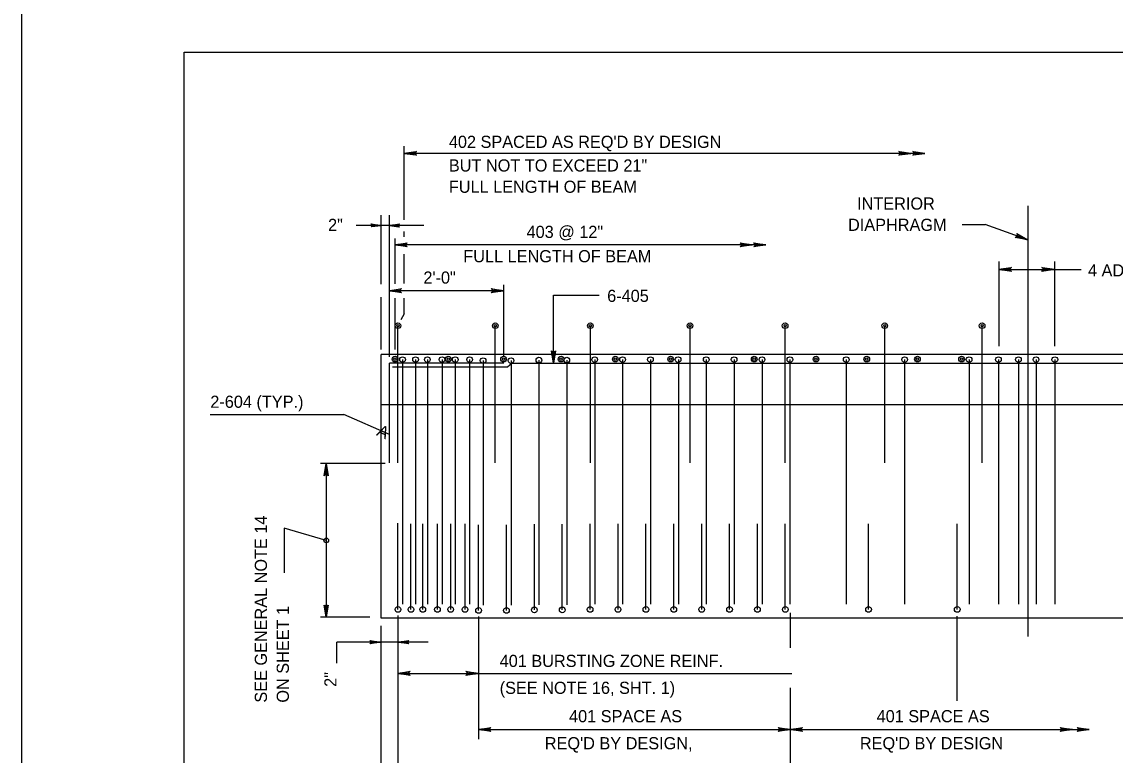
# Model space of a CAD drawing. Extents: x 637933 to 640019, y 298854 to 300042.
# Drawn here: x 637983.9 to 638253.5, y 299259.7 to 299440.6 of the extents above; entities that cross this region are included whole.
import ezdxf

# ---------------------------------------------------------------- set-up
doc = ezdxf.new("R2010")
doc.units = 0
doc.layers.add('1', color=7, linetype='Continuous')
doc.layers.add('PLT-BNDY', color=7, linetype='Continuous')

msp = doc.modelspace()

# ---------------------------------------------------------------- linework, layer by layer
at = {"layer": '1'}
for p, q in [((638023.93, 298869.12), (638023.93, 299433.12)), ((638023.93, 299433.12), (638809.94, 299433.12)), ((638078.22, 299391.78), (638078.22, 299409.92)), ((638206.58, 299408.17), (638078.22, 299408.17)), ((638231.96, 299395.21), (638231.96, 299288.98)), ((638072.53, 299375.88), (638072.53, 299392.9)), ((638074.53, 299359.78), (638074.53, 299392.9)), ((638083.04, 299390.4), (638066.36, 299390.4)), ((638078.22, 299387.54), (638078.22, 299388.89)), ((638215.72, 299390.58), (638221.43, 299390.58)), ((638231.96, 299386.81), (638221.43, 299390.58)), ((638075.94, 299375.99), (638075.94, 299387.15)), ((638167.35, 299385.6), (638075.94, 299385.6)), ((638078.22, 299376.1), (638078.22, 299383.29)), ((638224.76, 299381.47), (638224.76, 299360.57)), ((638238.51, 299381.47), (638238.51, 299360.57)), ((638224.76, 299379.54), (638245.11, 299379.54)), ((638074.53, 299357.93), (638074.53, 299375.73)), ((638102.78, 299357.93), (638102.78, 299375.73)), ((638072.53, 299359.78), (638072.53, 299372.68)), ((638102.78, 299374.23), (638074.53, 299374.23)), ((638075.94, 299359.76), (638075.94, 299372.46)), ((638078.22, 299368.6), (638078.22, 299372.46)), ((638115.02, 299357.01), (638115.02, 299373.17)), ((638115.02, 299373.17), (638126.28, 299373.17)), ((638078.22, 299368.6), (638077.4, 299367.09)), ((638076.65, 299331.81), (638076.65, 299365.65)), ((638076.65, 299365.65), (638076.65, 299365.65)), ((638076.65, 299365.65), (638076.65, 299365.65)), ((638076.65, 299365.65), (638076.65, 299365.65)), ((638076.65, 299365.65), (638076.65, 299365.65)), ((638100.65, 299331.81), (638100.65, 299365.65)), ((638100.65, 299365.65), (638100.65, 299365.65)), ((638100.65, 299365.65), (638100.65, 299365.65)), ((638100.65, 299365.65), (638100.65, 299365.65)), ((638100.65, 299365.65), (638100.65, 299365.65)), ((638124.09, 299331.81), (638124.09, 299365.65)), ((638124.65, 299365.65), (638124.65, 299365.65)), ((638124.65, 299365.65), (638124.65, 299365.65)), ((638124.65, 299365.65), (638124.65, 299365.65)), ((638124.65, 299365.65), (638124.65, 299365.65)), ((638148.65, 299331.81), (638148.65, 299365.65)), ((638148.65, 299365.65), (638148.65, 299365.65)), ((638148.65, 299365.65), (638148.65, 299365.65)), ((638148.65, 299365.65), (638148.65, 299365.65)), ((638148.65, 299365.65), (638148.65, 299365.65)), ((638172.09, 299331.81), (638172.09, 299365.65)), ((638172.65, 299365.65), (638172.65, 299365.65)), ((638172.65, 299365.65), (638172.65, 299365.65)), ((638172.65, 299365.65), (638172.65, 299365.65)), ((638172.65, 299365.65), (638172.65, 299365.65)), ((638196.65, 299331.81), (638196.65, 299365.65)), ((638196.65, 299365.65), (638196.65, 299365.65)), ((638196.65, 299365.65), (638196.65, 299365.65)), ((638196.65, 299365.65), (638196.65, 299365.65)), ((638196.65, 299365.65), (638196.65, 299365.65)), ((638220.65, 299331.81), (638220.65, 299365.65)), ((638220.65, 299365.65), (638220.65, 299365.65)), ((638220.65, 299365.65), (638220.65, 299365.65)), ((638220.65, 299365.65), (638220.65, 299365.65)), ((638220.65, 299365.65), (638220.65, 299365.65)), ((638072.53, 299293.53), (638072.53, 299358.53)), ((638298.76, 299358.53), (638072.53, 299358.53)), ((638074.53, 299331.81), (638074.53, 299356.43)), ((638102.78, 299356.43), (638074.53, 299356.43)), ((638075.94, 299357.4), (638075.94, 299357.4)), ((638075.94, 299357.4), (638075.94, 299357.4)), ((638075.94, 299357.4), (638075.94, 299357.4)), ((638075.94, 299357.4), (638075.94, 299357.4)), ((638077.78, 299357.28), (638077.78, 299357.28)), ((638077.78, 299357.28), (638077.78, 299357.28)), ((638077.78, 299357.28), (638077.78, 299357.28)), ((638077.78, 299357.28), (638077.78, 299357.28)), ((638077.78, 299357.28), (638077.78, 299296.94)), ((638080.98, 299357.28), (638080.98, 299357.28)), ((638080.98, 299357.28), (638080.98, 299357.28)), ((638080.98, 299357.28), (638080.98, 299357.28)), ((638080.98, 299357.28), (638080.98, 299357.28)), ((638080.98, 299357.28), (638080.98, 299296.94)), ((638083.9, 299357.28), (638083.9, 299357.28)), ((638083.9, 299357.28), (638083.9, 299357.28)), ((638083.9, 299357.28), (638083.9, 299357.28)), ((638083.9, 299357.28), (638083.9, 299357.28)), ((638083.9, 299357.28), (638083.9, 299296.94)), ((638087.51, 299357.28), (638087.51, 299357.28)), ((638087.51, 299357.28), (638087.51, 299357.28)), ((638087.51, 299357.28), (638087.51, 299357.28)), ((638087.51, 299357.28), (638087.51, 299357.28)), ((638087.51, 299357.28), (638087.51, 299296.94)), ((638089.05, 299357.4), (638089.05, 299357.4)), ((638089.05, 299357.4), (638089.05, 299357.4)), ((638089.05, 299357.4), (638089.05, 299357.4)), ((638089.05, 299357.4), (638089.05, 299357.4)), ((638090.78, 299357.28), (638090.78, 299357.28)), ((638090.78, 299357.28), (638090.78, 299357.28)), ((638090.78, 299357.28), (638090.78, 299357.28)), ((638090.78, 299357.28), (638090.78, 299357.28)), ((638090.78, 299357.28), (638090.78, 299296.94)), ((638094.32, 299357.28), (638094.32, 299357.28)), ((638094.32, 299357.28), (638094.32, 299357.28)), ((638094.32, 299357.28), (638094.32, 299357.28)), ((638094.32, 299357.28), (638094.32, 299357.28)), ((638094.32, 299357.28), (638094.32, 299296.94)), ((638097.65, 299357.03), (638097.65, 299357.03)), ((638097.65, 299357.03), (638097.65, 299357.03)), ((638097.65, 299357.03), (638097.65, 299357.03)), ((638097.65, 299357.03), (638097.65, 299357.03)), ((638097.65, 299357.03), (638097.65, 299296.69)), ((638102.69, 299357.4), (638102.69, 299357.4)), ((638102.69, 299357.4), (638102.69, 299357.4)), ((638102.69, 299357.4), (638102.69, 299357.4)), ((638102.69, 299357.4), (638102.69, 299357.4)), ((638104.78, 299356.43), (638103.65, 299355.43)), ((638104.53, 299357.03), (638104.53, 299357.03)), ((638104.53, 299357.03), (638104.53, 299357.03)), ((638104.53, 299357.03), (638104.53, 299357.03)), ((638104.53, 299357.03), (638104.53, 299357.03)), ((638104.53, 299357.03), (638104.53, 299296.69)), ((638104.78, 299356.43), (638298.64, 299356.43)), ((638111.4, 299357.15), (638111.4, 299357.15)), ((638111.4, 299357.15), (638111.4, 299357.15)), ((638111.4, 299357.15), (638111.4, 299357.15)), ((638111.4, 299357.15), (638111.4, 299357.15)), ((638111.4, 299357.15), (638111.4, 299296.81)), ((638115.02, 299356.43), (638115.02, 299357.01)), ((638116.87, 299357.4), (638116.87, 299357.4)), ((638116.87, 299357.4), (638116.87, 299357.4)), ((638116.87, 299357.4), (638116.87, 299357.4)), ((638116.87, 299357.4), (638116.87, 299357.4)), ((638118.28, 299357.15), (638118.28, 299357.15)), ((638118.28, 299357.15), (638118.28, 299357.15)), ((638118.28, 299357.15), (638118.28, 299357.15)), ((638118.28, 299357.15), (638118.28, 299357.15)), ((638118.28, 299357.15), (638118.28, 299296.81)), ((638125.15, 299357.28), (638125.15, 299357.28)), ((638125.15, 299357.28), (638125.15, 299357.28)), ((638125.15, 299357.28), (638125.15, 299357.28)), ((638125.15, 299357.28), (638125.15, 299357.28)), ((638125.15, 299357.28), (638125.15, 299296.94)), ((638130.24, 299357.4), (638130.24, 299357.4)), ((638130.24, 299357.4), (638130.24, 299357.4)), ((638130.24, 299357.4), (638130.24, 299357.4)), ((638130.24, 299357.4), (638130.24, 299357.4)), ((638132.03, 299357.28), (638132.03, 299357.28)), ((638132.03, 299357.28), (638132.03, 299357.28)), ((638132.03, 299357.28), (638132.03, 299357.28)), ((638132.03, 299357.28), (638132.03, 299357.28)), ((638132.03, 299357.28), (638132.03, 299296.94)), ((638138.9, 299357.28), (638138.9, 299357.28)), ((638138.9, 299357.28), (638138.9, 299357.28)), ((638138.9, 299357.28), (638138.9, 299357.28)), ((638138.9, 299357.28), (638138.9, 299357.28)), ((638138.9, 299357.28), (638138.9, 299296.94)), ((638143.88, 299357.4), (638143.88, 299357.4)), ((638143.88, 299357.4), (638143.88, 299357.4)), ((638143.88, 299357.4), (638143.88, 299357.4)), ((638143.88, 299357.4), (638143.88, 299357.4)), ((638145.78, 299357.28), (638145.78, 299357.28)), ((638145.78, 299357.28), (638145.78, 299357.28)), ((638145.78, 299357.28), (638145.78, 299357.28)), ((638145.78, 299357.28), (638145.78, 299357.28)), ((638145.78, 299357.28), (638145.78, 299296.94)), ((638151.92, 299357.28), (638151.92, 299357.28)), ((638152.02, 299357.28), (638152.02, 299357.28)), ((638152.21, 299357.28), (638152.21, 299357.28)), ((638152.65, 299357.28), (638152.65, 299357.28)), ((638152.65, 299357.28), (638152.65, 299357.28)), ((638152.65, 299357.28), (638152.65, 299357.28)), ((638152.65, 299357.28), (638152.65, 299357.28)), ((638152.65, 299357.28), (638152.65, 299296.94)), ((638159.53, 299357.28), (638159.53, 299357.28)), ((638159.53, 299357.28), (638159.53, 299357.28)), ((638159.53, 299357.28), (638159.53, 299357.28)), ((638159.53, 299357.28), (638159.53, 299357.28)), ((638159.53, 299357.28), (638159.53, 299296.94)), ((638164.47, 299357.4), (638164.47, 299357.4)), ((638164.47, 299357.4), (638164.47, 299357.4)), ((638164.47, 299357.4), (638164.47, 299357.4)), ((638164.47, 299357.4), (638164.47, 299357.4)), ((638166.4, 299357.28), (638166.4, 299357.28)), ((638166.4, 299357.28), (638166.4, 299357.28)), ((638166.4, 299357.28), (638166.4, 299357.28)), ((638166.4, 299357.28), (638166.4, 299357.28)), ((638166.4, 299357.28), (638166.4, 299296.94)), ((638173.28, 299357.28), (638173.28, 299357.28)), ((638173.28, 299357.28), (638173.28, 299357.28)), ((638173.28, 299357.28), (638173.28, 299357.28)), ((638173.28, 299357.28), (638173.28, 299357.28)), ((638173.28, 299357.28), (638173.28, 299296.94)), ((638179.72, 299357.4), (638179.72, 299357.4)), ((638179.72, 299357.4), (638179.72, 299357.4)), ((638179.72, 299357.4), (638179.72, 299357.4)), ((638179.72, 299357.4), (638179.72, 299357.4)), ((638187.17, 299357.28), (638187.17, 299296.94)), ((638187.17, 299357.28), (638187.17, 299357.28)), ((638187.17, 299357.28), (638187.17, 299357.28)), ((638187.17, 299357.28), (638187.17, 299357.28)), ((638187.17, 299357.28), (638187.17, 299357.28)), ((638192.22, 299357.4), (638192.22, 299357.4)), ((638192.22, 299357.4), (638192.22, 299357.4)), ((638192.22, 299357.4), (638192.22, 299357.4)), ((638192.22, 299357.4), (638192.22, 299357.4)), ((638201.56, 299357.28), (638201.56, 299296.94)), ((638201.56, 299357.28), (638201.56, 299357.28)), ((638201.56, 299357.28), (638201.56, 299357.28)), ((638201.56, 299357.28), (638201.56, 299357.28)), ((638201.56, 299357.28), (638201.56, 299357.28)), ((638204.72, 299357.4), (638204.72, 299357.4)), ((638204.72, 299357.4), (638204.72, 299357.4)), ((638204.72, 299357.4), (638204.72, 299357.4)), ((638204.72, 299357.4), (638204.72, 299357.4)), ((638215.61, 299357.4), (638215.61, 299357.4)), ((638215.61, 299357.4), (638215.61, 299357.4)), ((638215.61, 299357.4), (638215.61, 299357.4)), ((638215.61, 299357.4), (638215.61, 299357.4)), ((638217.22, 299357.4), (638217.22, 299357.4)), ((638217.22, 299357.4), (638217.22, 299357.4)), ((638217.22, 299357.4), (638217.22, 299357.4)), ((638217.47, 299357.28), (638217.47, 299296.94)), ((638217.47, 299357.28), (638217.47, 299357.28)), ((638217.47, 299357.28), (638217.47, 299357.28)), ((638217.47, 299357.28), (638217.47, 299357.28)), ((638217.47, 299357.28), (638217.47, 299357.28)), ((638224.7, 299357.28), (638224.7, 299296.94)), ((638224.7, 299357.28), (638224.7, 299357.28)), ((638224.7, 299357.28), (638224.7, 299357.28)), ((638224.7, 299357.28), (638224.7, 299357.28)), ((638224.7, 299357.28), (638224.7, 299357.28)), ((638229.62, 299357.28), (638229.62, 299296.94)), ((638229.62, 299357.28), (638229.62, 299357.28)), ((638229.62, 299357.28), (638229.62, 299357.28)), ((638229.62, 299357.28), (638229.62, 299357.28)), ((638229.62, 299357.28), (638229.62, 299357.28)), ((638233.96, 299357.28), (638233.96, 299296.94)), ((638233.96, 299357.28), (638233.96, 299357.28)), ((638233.96, 299357.28), (638233.96, 299357.28)), ((638233.96, 299357.28), (638233.96, 299357.28)), ((638233.96, 299357.28), (638233.96, 299357.28)), ((638238.59, 299357.28), (638238.59, 299296.94)), ((638238.59, 299357.28), (638238.59, 299357.28)), ((638238.59, 299357.28), (638238.59, 299357.28)), ((638238.59, 299357.28), (638238.59, 299357.28)), ((638238.59, 299357.28), (638238.59, 299357.28)), ((638103.65, 299355.43), (638075.28, 299355.43)), ((638297.73, 299346.15), (638072.53, 299346.15)), ((638030.36, 299343.75), (638063.31, 299343.75)), ((638074.53, 299338.83), (638063.31, 299343.75)), ((638073.46, 299331.65), (638057.53, 299331.65)), ((638058.98, 299331.65), (638058.98, 299293.73)), ((638076.65, 299295.65), (638076.65, 299316.9)), ((638079.86, 299295.65), (638079.86, 299316.78)), ((638082.78, 299295.65), (638082.78, 299316.78)), ((638086.39, 299295.65), (638086.39, 299316.78)), ((638089.65, 299295.65), (638089.65, 299316.78)), ((638093.19, 299295.65), (638093.19, 299316.78)), ((638096.53, 299295.4), (638096.53, 299316.53)), ((638103.4, 299295.4), (638103.4, 299316.53)), ((638110.28, 299295.53), (638110.28, 299316.65)), ((638117.15, 299295.53), (638117.15, 299316.65)), ((638124.03, 299295.65), (638124.03, 299316.78)), ((638130.9, 299295.65), (638130.9, 299316.78)), ((638137.78, 299295.65), (638137.78, 299316.78)), ((638144.65, 299295.65), (638144.65, 299316.78)), ((638151.53, 299295.65), (638151.53, 299316.78)), ((638158.4, 299295.65), (638158.4, 299316.78)), ((638165.28, 299295.65), (638165.28, 299316.78)), ((638172.15, 299295.65), (638172.15, 299316.78)), ((638192.66, 299295.65), (638192.66, 299316.78)), ((638192.66, 299316.78), (638192.66, 299316.78)), ((638214.53, 299295.65), (638214.53, 299316.78)), ((638058.98, 299312.69), (638048.56, 299315.67)), ((638048.56, 299315.67), (638048.56, 299304.66)), ((638076.65, 299294.15), (638076.65, 299240.18)), ((638173.4, 299286.17), (638173.4, 299294.84)), ((638214.53, 299295.65), (638214.53, 299295.65)), ((638214.53, 299295.65), (638214.53, 299295.65)), ((638214.53, 299295.65), (638214.53, 299295.65)), ((638069.68, 299293.73), (638057.53, 299293.73)), ((638293.89, 299293.53), (638072.53, 299293.53)), ((638072.53, 299227.1), (638072.53, 299291.6)), ((638096.53, 299293.9), (638096.53, 299263.64)), ((638214.53, 299273.1), (638214.53, 299294.01)), ((638072.28, 299287.58), (638061.56, 299287.58)), ((638061.56, 299282.43), (638061.56, 299287.58)), ((638076.65, 299287.58), (638072.28, 299287.58)), ((638084.06, 299287.58), (638076.65, 299287.58)), ((638076.65, 299279.83), (638173.76, 299279.83)), ((638173.4, 299236.01), (638173.4, 299276.34)), ((638096.53, 299266.03), (638173.4, 299266.03)), ((638173.4, 299266.03), (638247.08, 299266.03))]:
    msp.add_line(p, q, dxfattribs=at)
for points in [[(638081.08, 299407.82), (638080.97, 299408.02), (638078.22, 299408.17), (638081.08, 299407.82), (638081.22, 299407.69), (638078.22, 299408.17), (638080.97, 299408.31), (638081.07, 299408.51), (638078.22, 299408.17), (638081.22, 299408.65), (638081.07, 299408.51)], [(638200.26, 299408.53), (638200.36, 299408.33), (638203.11, 299408.17), (638200.26, 299408.53), (638200.11, 299408.66), (638203.11, 299408.17), (638200.37, 299408.04), (638200.27, 299407.83), (638203.11, 299408.17), (638200.11, 299407.7), (638200.27, 299407.83)], [(638203.73, 299408.53), (638203.83, 299408.33), (638206.58, 299408.17), (638203.73, 299408.53), (638203.58, 299408.66), (638206.58, 299408.17), (638203.84, 299408.04), (638203.74, 299407.83), (638206.58, 299408.17), (638203.58, 299407.7), (638203.74, 299407.83)], [(638070.15, 299390.65), (638070.28, 299390.53), (638072.53, 299390.4), (638070.15, 299390.65), (638070.03, 299390.78), (638072.53, 299390.4), (638070.28, 299390.28), (638070.15, 299390.15), (638072.53, 299390.4), (638070.03, 299390.03), (638070.15, 299390.15)], [(638076.9, 299390.03), (638076.78, 299390.28), (638074.53, 299390.4), (638076.9, 299390.03), (638077.03, 299390.03), (638074.53, 299390.4), (638076.78, 299390.53), (638076.9, 299390.65), (638074.53, 299390.4), (638077.03, 299390.78), (638076.9, 299390.65)], [(638078.76, 299385.24), (638078.65, 299385.45), (638075.91, 299385.6), (638078.76, 299385.24), (638078.91, 299385.12), (638075.91, 299385.6), (638078.65, 299385.74), (638078.75, 299385.94), (638075.91, 299385.6), (638078.91, 299386.08), (638078.75, 299385.94)], [(638161.16, 299385.96), (638161.26, 299385.75), (638164.01, 299385.6), (638161.16, 299385.96), (638161.01, 299386.08), (638164.01, 299385.6), (638161.26, 299385.47), (638161.16, 299385.26), (638164.01, 299385.6), (638161.01, 299385.12), (638161.16, 299385.26)], [(638164.5, 299385.96), (638164.61, 299385.75), (638167.35, 299385.6), (638164.5, 299385.96), (638164.35, 299386.08), (638167.35, 299385.6), (638164.61, 299385.47), (638164.51, 299385.26), (638167.35, 299385.6), (638164.35, 299385.12), (638164.51, 299385.26)], [(638229.29, 299388.24), (638229.33, 299387.91), (638231.96, 299386.81), (638229.29, 299388.24), (638229.2, 299388.44), (638231.96, 299386.81), (638229.23, 299387.63), (638229.04, 299387.54), (638231.96, 299386.81), (638228.84, 299387.45), (638229.04, 299387.54)], [(638227.76, 299379.16), (638227.64, 299379.41), (638224.76, 299379.54), (638227.76, 299379.16), (638227.89, 299379.04), (638224.76, 299379.54), (638227.64, 299379.79), (638227.76, 299379.91), (638224.76, 299379.54), (638227.89, 299380.04), (638227.76, 299379.91)], [(638235.51, 299379.91), (638235.63, 299379.79), (638238.51, 299379.54), (638235.51, 299379.91), (638235.38, 299380.04), (638238.51, 299379.54), (638235.63, 299379.41), (638235.51, 299379.29), (638238.51, 299379.54), (638235.38, 299379.04), (638235.51, 299379.29)], [(638077.38, 299373.93), (638077.23, 299374.08), (638074.53, 299374.23), (638077.38, 299373.93), (638077.53, 299373.78), (638074.53, 299374.23), (638077.23, 299374.38), (638077.38, 299374.68), (638074.53, 299374.23), (638077.53, 299374.83), (638077.38, 299374.68)], [(638099.78, 299374.68), (638099.93, 299374.38), (638102.78, 299374.23), (638099.78, 299374.68), (638099.63, 299374.83), (638102.78, 299374.23), (638099.93, 299374.08), (638099.78, 299373.93), (638102.78, 299374.23), (638099.63, 299373.78), (638099.78, 299373.93)], [(638115.37, 299359.28), (638115.17, 299359.18), (638115.02, 299356.43), (638115.37, 299359.28), (638115.5, 299359.43), (638115.02, 299356.43), (638114.88, 299359.17), (638114.68, 299359.27), (638115.02, 299356.43), (638114.54, 299359.43), (638114.68, 299359.27)], [(638058.62, 299328.8), (638058.83, 299328.9), (638058.98, 299331.65), (638058.62, 299328.8), (638058.49, 299328.65), (638058.98, 299331.65), (638059.11, 299328.91), (638059.32, 299328.81), (638058.98, 299331.65), (638059.46, 299328.65), (638059.32, 299328.81)], [(638059.34, 299296.59), (638059.13, 299296.48), (638058.98, 299293.73), (638059.34, 299296.59), (638059.46, 299296.73), (638058.98, 299293.73), (638058.84, 299296.48), (638058.64, 299296.58), (638058.98, 299293.73), (638058.5, 299296.73), (638058.64, 299296.58)], [(638069.9, 299287.83), (638070.03, 299287.7), (638072.28, 299287.58), (638069.9, 299287.83), (638069.78, 299287.95), (638072.28, 299287.58), (638070.03, 299287.45), (638069.9, 299287.33), (638072.28, 299287.58), (638069.78, 299287.2), (638069.9, 299287.33)], [(638079.15, 299287.33), (638079.03, 299287.45), (638076.65, 299287.58), (638079.15, 299287.33), (638079.28, 299287.2), (638076.65, 299287.58), (638079.03, 299287.7), (638079.15, 299287.83), (638076.65, 299287.58), (638079.28, 299287.95), (638079.15, 299287.83)], [(638079.5, 299279.53), (638079.35, 299279.68), (638076.65, 299279.83), (638079.5, 299279.53), (638079.65, 299279.38), (638076.65, 299279.83), (638079.35, 299279.98), (638079.5, 299280.28), (638076.65, 299279.83), (638079.65, 299280.43), (638079.5, 299280.28)], [(638093.53, 299280.28), (638093.68, 299279.98), (638096.53, 299279.83), (638093.53, 299280.28), (638093.38, 299280.43), (638096.53, 299279.83), (638093.68, 299279.68), (638093.53, 299279.53), (638096.53, 299279.83), (638093.38, 299279.38), (638093.53, 299279.53)], [(638099.38, 299265.67), (638099.27, 299265.87), (638096.53, 299266.03), (638099.38, 299265.67), (638099.53, 299265.54), (638096.53, 299266.03), (638099.27, 299266.16), (638099.37, 299266.36), (638096.53, 299266.03), (638099.53, 299266.5), (638099.37, 299266.36)], [(638170.54, 299266.38), (638170.65, 299266.18), (638173.4, 299266.03), (638170.54, 299266.38), (638170.4, 299266.51), (638173.4, 299266.03), (638170.65, 299265.89), (638170.55, 299265.69), (638173.4, 299266.03), (638170.4, 299265.55), (638170.55, 299265.69)], [(638176.25, 299265.67), (638176.15, 299265.87), (638173.4, 299266.03), (638176.25, 299265.67), (638176.4, 299265.54), (638173.4, 299266.03), (638176.14, 299266.16), (638176.24, 299266.36), (638173.4, 299266.03), (638176.4, 299266.5), (638176.24, 299266.36)], [(638240.06, 299266.38), (638240.16, 299266.18), (638242.91, 299266.03), (638240.06, 299266.38), (638239.91, 299266.51), (638242.91, 299266.03), (638240.16, 299265.89), (638240.06, 299265.69), (638242.91, 299266.03), (638239.91, 299265.55), (638240.06, 299265.69)], [(638244.22, 299266.38), (638244.33, 299266.18), (638247.08, 299266.03), (638244.22, 299266.38), (638244.08, 299266.51), (638247.08, 299266.03), (638244.33, 299265.89), (638244.23, 299265.69), (638247.08, 299266.03), (638244.08, 299265.55), (638244.23, 299265.69)]]:
    msp.add_lwpolyline(points, dxfattribs=at)
for centre, radius in [((638076.65, 299365.65), 0.7), ((638076.67, 299365.68), 0.274), ((638100.65, 299365.65), 0.7), ((638100.67, 299365.68), 0.274), ((638124.09, 299365.65), 0.7), ((638124.1, 299365.68), 0.274), ((638148.65, 299365.65), 0.7), ((638148.67, 299365.68), 0.274), ((638172.09, 299365.65), 0.7), ((638172.1, 299365.68), 0.274), ((638196.65, 299365.65), 0.7), ((638196.67, 299365.68), 0.274), ((638220.65, 299365.65), 0.7), ((638220.67, 299365.68), 0.274), ((638075.94, 299357.4), 0.7), ((638075.95, 299357.4), 0.3), ((638077.78, 299357.28), 0.7), ((638080.98, 299357.28), 0.7), ((638083.9, 299357.28), 0.7), ((638087.51, 299357.28), 0.7), ((638089.05, 299357.4), 0.7), ((638089.05, 299357.4), 0.3), ((638090.78, 299357.28), 0.7), ((638094.32, 299357.28), 0.7), ((638097.65, 299357.03), 0.7), ((638102.69, 299357.4), 0.7), ((638102.69, 299357.4), 0.3), ((638104.53, 299357.03), 0.7), ((638111.4, 299357.15), 0.7), ((638116.87, 299357.4), 0.7), ((638116.87, 299357.4), 0.3), ((638118.28, 299357.15), 0.7), ((638125.15, 299357.28), 0.7), ((638130.24, 299357.4), 0.7), ((638130.24, 299357.4), 0.3), ((638132.03, 299357.28), 0.7), ((638138.9, 299357.28), 0.7), ((638143.88, 299357.4), 0.7), ((638143.88, 299357.4), 0.3), ((638145.71, 299357.28), 0.7), ((638152.65, 299357.28), 0.7), ((638159.53, 299357.28), 0.7), ((638164.47, 299357.4), 0.7), ((638164.47, 299357.4), 0.3), ((638166.4, 299357.28), 0.7), ((638173.28, 299357.28), 0.7), ((638179.72, 299357.4), 0.7), ((638179.72, 299357.4), 0.3), ((638187.17, 299357.28), 0.7), ((638192.22, 299357.4), 0.7), ((638192.22, 299357.4), 0.3), ((638201.56, 299357.28), 0.7), ((638204.72, 299357.4), 0.7), ((638204.72, 299357.4), 0.3), ((638215.61, 299357.4), 0.7), ((638215.61, 299357.4), 0.3), ((638217.47, 299357.28), 0.7), ((638224.7, 299357.28), 0.7), ((638229.62, 299357.28), 0.7), ((638233.96, 299357.28), 0.7), ((638238.59, 299357.28), 0.7), ((638058.98, 299312.69), 0.575), ((638076.65, 299295.65), 0.7), ((638079.86, 299295.65), 0.7), ((638082.78, 299295.65), 0.7), ((638086.39, 299295.65), 0.7), ((638089.65, 299295.65), 0.7), ((638093.19, 299295.65), 0.7), ((638096.53, 299295.4), 0.7), ((638103.4, 299295.4), 0.7), ((638110.28, 299295.53), 0.7), ((638117.15, 299295.53), 0.7), ((638124.03, 299295.65), 0.7), ((638130.9, 299295.65), 0.7), ((638137.78, 299295.65), 0.7), ((638144.65, 299295.65), 0.7), ((638151.53, 299295.65), 0.7), ((638158.4, 299295.65), 0.7), ((638165.28, 299295.65), 0.7), ((638172.15, 299295.65), 0.7), ((638192.66, 299295.65), 0.7), ((638214.53, 299295.65), 0.7)]:
    msp.add_circle(centre, radius, dxfattribs=at)
at = {"layer": 'PLT-BNDY'}
msp.add_lwpolyline([(637983.93, 299448.12), (638824.93, 299448.12), (638824.93, 298854.12), (637983.93, 298854.12)], close=True, dxfattribs=at)

# ---------------------------------------------------------------- texts
at = {"layer": '1'}
for s, p in [("402 SPACED AS REQ'D BY DESIGN", (638089.2, 299409.52)), ('BUT NOT TO EXCEED 21"', (638089.2, 299403.69)), ('FULL LENGTH OF BEAM', (638089.2, 299398.44)), ('  INTERIOR', (638187.61, 299394.29)), ('2"', (638059.42, 299389.02)), ('DIAPHRAGM', (638187.61, 299389.04)), ('403 @ 12"', (638108.36, 299387.3)), ('FULL LENGTH OF BEAM', (638092.76, 299381.3)), ('4 ADDT\'L 401 @ 4"', (638246.76, 299377.8)), ('2\'-0"', (638082.92, 299376.03)), ('6-405', (638128.23, 299371.52)), ('2-604 (TYP.)', (638030.39, 299345.39)), ('401 BURSTING ZONE REINF.', (638101.73, 299281.45)), ('(SEE NOTE 16, SHT. 1)', (638101.73, 299274.81)), ('401 SPACE AS', (638118.83, 299267.81)), ('401 SPACE AS', (638194.66, 299267.81)), ("REQ'D BY DESIGN,", (638112.85, 299261.14)), ("REQ'D BY DESIGN", (638190.53, 299261.14))]:
    msp.add_text(s, height=3, dxfattribs=at).set_placement(p)
for s, rotation, p in [('A', 336.3048, (638071.18, 299338.66)), ('SEE GENERAL NOTE 14', 90, (638044.36, 299272.65)), ('ON SHEET 1', 90, (638049.76, 299272.65)), ('2"', 90, (638061.5, 299276.54))]:
    msp.add_text(s, height=3, rotation=rotation, dxfattribs=at).set_placement(p)

doc.saveas('drawing.dxf')
